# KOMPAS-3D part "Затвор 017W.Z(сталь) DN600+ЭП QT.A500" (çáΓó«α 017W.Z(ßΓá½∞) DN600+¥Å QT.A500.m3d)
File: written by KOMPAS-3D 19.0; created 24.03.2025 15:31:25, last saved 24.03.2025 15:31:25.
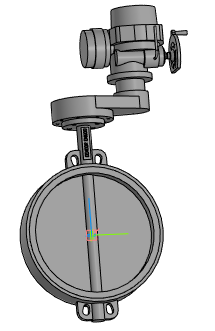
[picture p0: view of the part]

Document properties: Полное имя файла: Затвор 017W.Z(сталь) DN600+ЭП QT.A500.a3d

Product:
- Part/product: Затвор 017W.Z(сталь) DN600+ЭП QT.A500
    Масса: 429.246

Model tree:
1. Операция без истории:1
